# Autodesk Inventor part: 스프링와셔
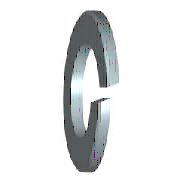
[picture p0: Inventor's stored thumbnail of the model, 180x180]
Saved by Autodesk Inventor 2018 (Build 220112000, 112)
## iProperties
Created: 2012-02
Part Number: 스프링와셔
Material: 강철, 연강
Description: 스프링 와셔
Document SubType Name: Modeling
Standard: JIS B 1251
Designer: mduedu
Standards Organization: JIS
Language: ko-KR
Size Designation: 번호 2 4
Categories: <MemberInstance><Categories><Category DisplayName="조임쇠" InternalName="e4da775c-781d-43d5-af7c-5136215cf5a6" Mnemonic="FSTN"><Category DisplayName="와셔" InternalN
Density: 1 g/cm^3
Appearance: 파란색 - 벽 페인트 - 광택
IsCustomPart: 1
Author: mduedu
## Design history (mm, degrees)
sketch "스케치1"
  geometry: C1 r 3.8 at (0, 0); C2 r 2.05 at (0, 0); 1 further point
  constraints: 2 centre point, 2 coincident
  dimensions: "d0" = 4.1 diameter of C2 (= SD1); "d1" = 7.6 diameter of C1 (= SD2)
extrude "본체" new body sketch "스케치1" distance "d2" = 1 (= SD); taper "d3" = 0 deg
sketch "스케치2"
  geometry: L1 (0, -2.05)-(0, 2.05) reference; L2 (1, 3.8)-(1, -3.8) reference; L3 (-1.2, 0)-(7.2, 0) reference; L4 (0, -0.2)-(1, 0.164); L5 (0, 0.2)-(1, 0.564)
  constraints: 4 end point, 4 point on line, 1 parallel
  dimensions: "d4" = 0.2 distance from line of L3 L4.start (= 0.2 x SD); "d5" = 0.2 distance from line of L3 L5.start (= 0.2 x SD); "d6" = 70 deg angle of L2 L4 (= FAWI)
extrude "절단부" cut sketch "스케치2" stored distance "d7" = 1 (= SD); taper "d8" = 0 deg
workaxis "Work Axis1"
workplane "Work Plane1"
body "Solid1"
other parameters: "SD1" = 4.1 [user parameter; used in 1 equation term], "SD2" = 7.6 [user parameter; used in 1 equation term], "SD" = 1 [user parameter; used in 4 equation terms], "FAWI" = 70 deg [user parameter; used in 1 equation term], "d9" = 0, "d10" = 0, "d11" = 0, "d12" = 0, "SDI" = 1.4 [user parameter], "NND" = 4 [user parameter]
